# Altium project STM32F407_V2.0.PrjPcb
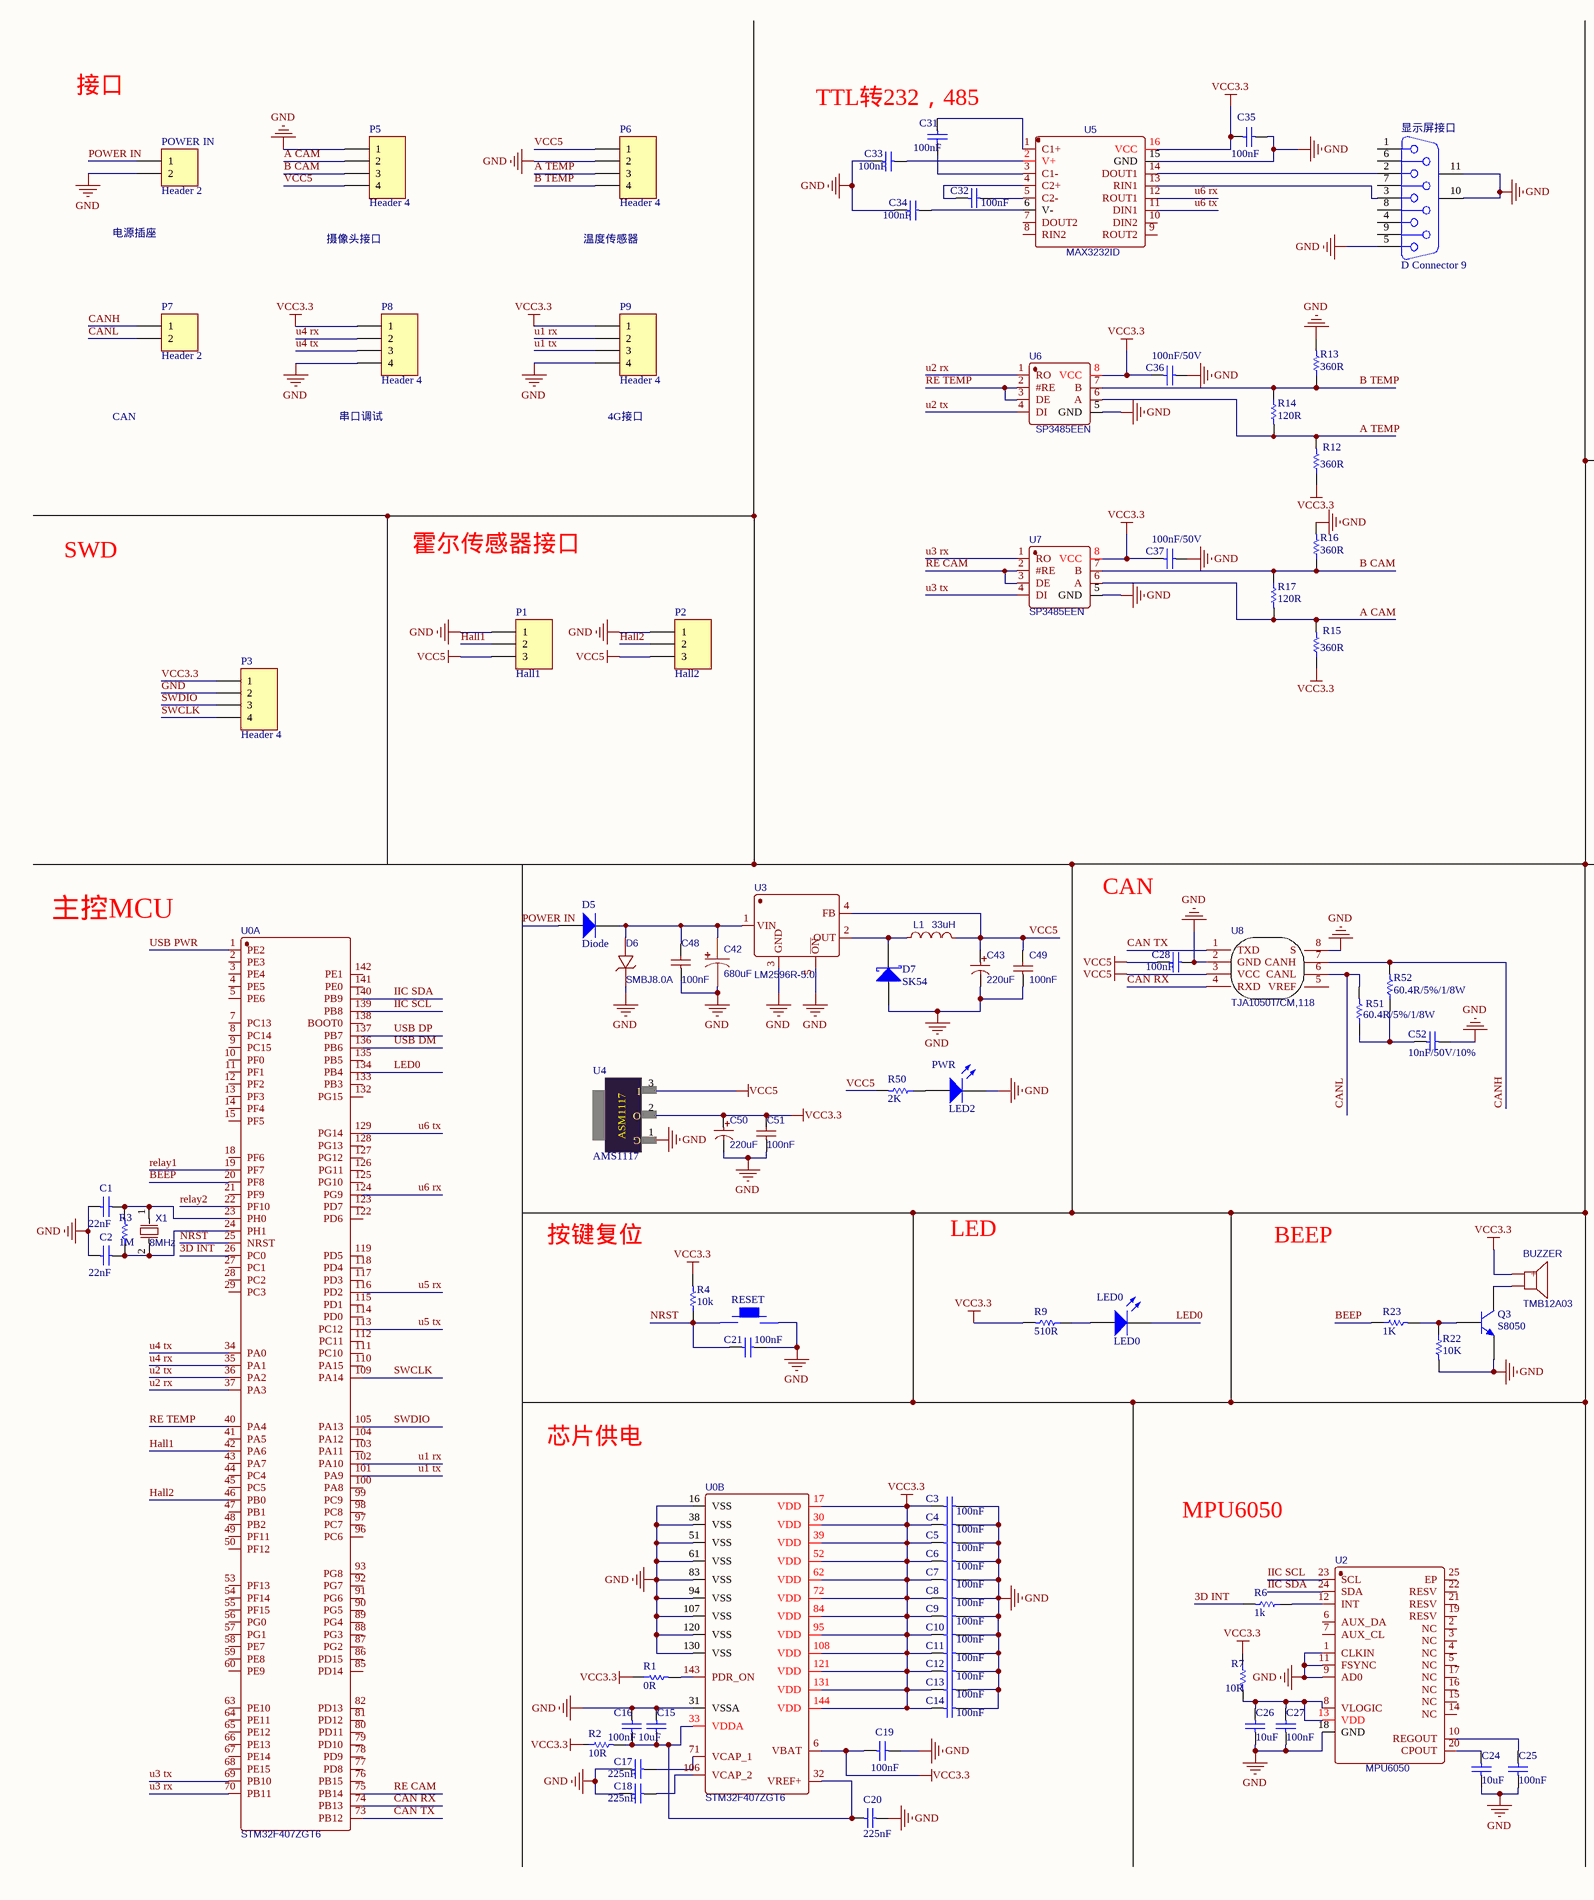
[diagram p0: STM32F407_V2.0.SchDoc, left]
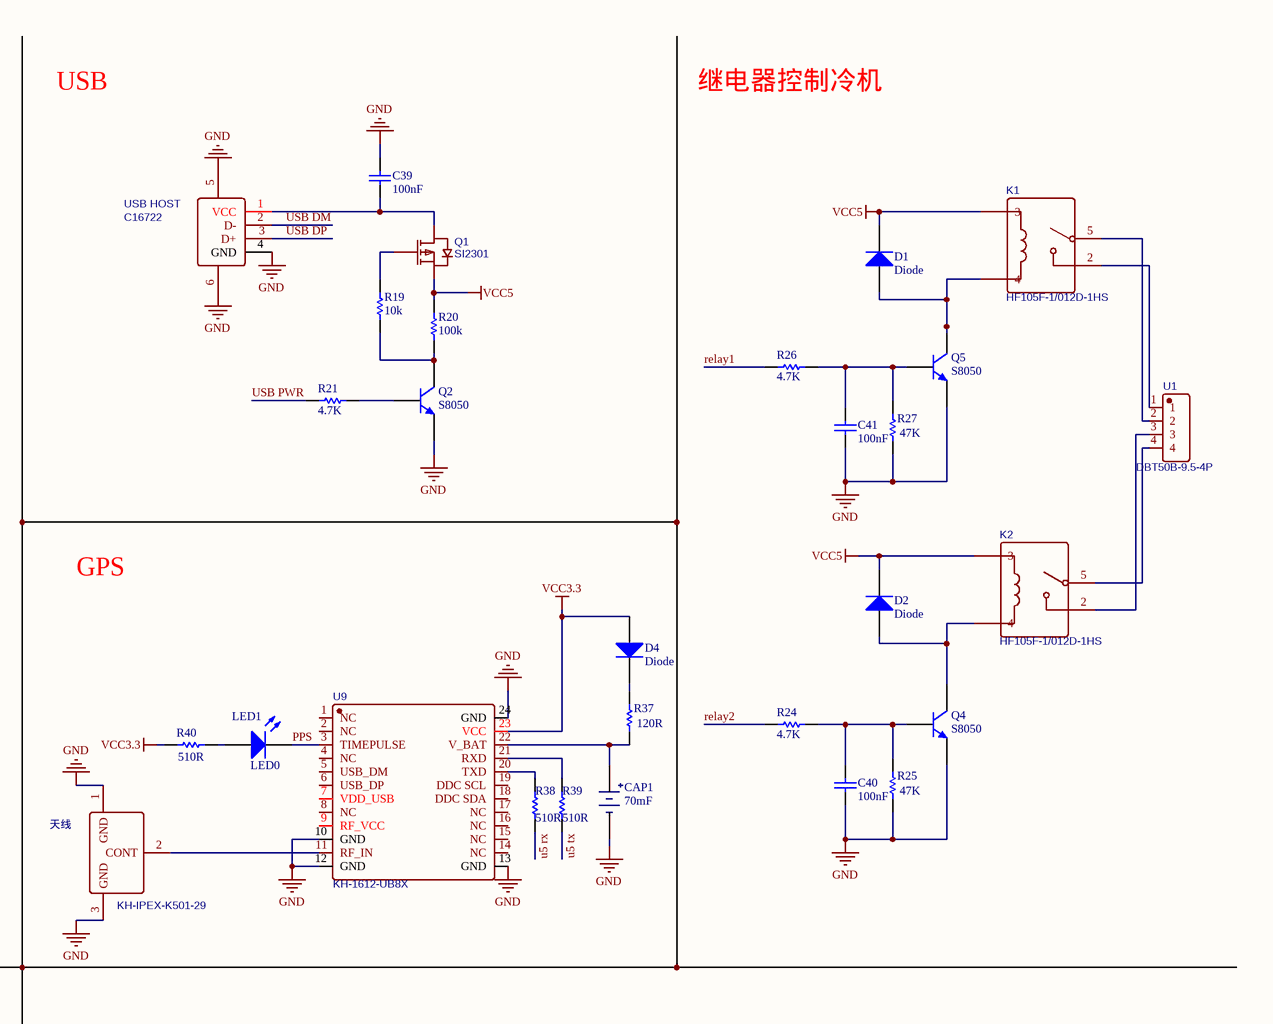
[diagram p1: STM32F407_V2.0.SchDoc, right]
1 sheet, 115 parts. Net scope: global (net labels, ports and power ports of the same name join across sheets).
Board file: STM32F407_V2.0.PcbDoc

## Sheet STM32F407_V2.0.SchDoc
size A2

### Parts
BUZZER  TMB12A03  [BUZ-TH_BD12.0-P7.60-D0.6-FD]
C1  22nF  [SMD_CAP_0603]
C2  22nF  [SMD_CAP_0603]
C3  100nF  [SMD_CAP_0603]
C4  100nF  [SMD_CAP_0603]
C5  100nF  [SMD_CAP_0603]
C6  100nF  [SMD_CAP_0603]
C7  100nF  [SMD_CAP_0603]
C8  100nF  [SMD_CAP_0603]
C9  100nF  [SMD_CAP_0603]
C10  100nF  [SMD_CAP_0603]
C11  100nF  [SMD_CAP_0603]
C12  100nF  [SMD_CAP_0603]
C13  100nF  [SMD_CAP_0603]
C14  100nF  [SMD_CAP_0603]
C15  10uF  [SMD_CAP_0603]
C16  100nF  [SMD_CAP_0603]
C17  225nF  [SMD_CAP_0603]
C18  225nF  [SMD_CAP_0603]
C19  100nF  [SMD_CAP_0603]
C20  225nF  [SMD_CAP_0603]
C21  100nF  [SMD_CAP_0603]
C24  10uF  [SMD_CAP_0603]
C25  100nF  [SMD_CAP_0603]
C26  10uF  [SMD_CAP_0603]
C27  100nF  [SMD_CAP_0603]
C28  100nF  [SMD_CAP_0603]
C31  100nF  [SMD_CAP_0603]
C32  100nF  [SMD_CAP_0603]
C33  100nF  [SMD_CAP_0603]
C34  100nF  [SMD_CAP_0603]
C35  100nF  [SMD_CAP_0603]
C36  100nF/50V  [SMD_CAP_0603]
C37  100nF/50V  [SMD_CAP_0603]
C39  100nF  [SMD_CAP_0603]
C40  100nF  [SMD_CAP_0603]
C41  100nF  [SMD_CAP_0603]
C42  680uF  [CAP-TH_BD8.0-P3.50-D1.0-FD]
C43  220uF  [CAP-TH_BD8.0-P3.50-D1.0-FD]
C48  100nF  [SMD_CAP_0603]
C49  100nF  [SMD_CAP_0603]
C50  220uF  [CAP-TH_BD8.0-P3.50-D1.0-FD]
C51  100nF  [SMD_CAP_0603]
C52  10nF/50V/10%  [SMD_CAP_0603]
CAP1  70mF  [CAP-TH_XH414HG]
D1  Diode  [SMC]
D2  Diode  [SMC]
D4  Diode  [SMC]
D5  Diode  [SMC]
D6  SMBJ8.0A  [SMB_L4.6-W3.6-LS5.3-RD]
D7  SK54  [SMB]
K1  HF105F-1/012D-1HS  [RELAY-TH_HF105F-XXX-1HXXX-XXX]
K2  HF105F-1/012D-1HS  [RELAY-TH_HF105F-XXX-1HXXX-XXX]
L1  33uH  [IND-SMD_L7.0-W6.8]
LED0  LED0  [3.2X1.6X1.1]
LED1  LED0  [3.2X1.6X1.1]
P1  Hall1  [HDR1X3]
P2  Hall2  [HDR1X3]
P3  Header 4  [HDR1X4]
P5  Header 4  [HDR1X4]
P6  Header 4  [HDR1X4]
P7  Header 2  [HDR1X2]
P8  Header 4  [HDR1X4]
P9  Header 4  [HDR1X4]
POWER_IN  Header 2  [HDR1X2]
PWR  LED2  [3.2X1.6X1.1]
Q1  SI2301  [SOT-23-3_L2.9-W1.3-P1.90-LS2.4-BR]
Q2  S8050  [NUP2105LT1G]
Q3  S8050  [NUP2105LT1G]
Q4  S8050  [NUP2105LT1G]
Q5  S8050  [NUP2105LT1G]
R1  0R  [SMD_RES_0603]
R2  10R  [SMD_RES_0603]
R3  1M  [SMD_RES_0603]
R4  10k  [SMD_RES_0603]
R6  1k  [SMD_RES_0603]
R7  10R  [SMD_RES_0603]
R9  510R  [SMD_RES_0603]
R12  360R  [SMD_RES_0603]
R13  360R  [SMD_RES_0603]
R14  120R  [SMD_RES_0603]
R15  360R  [SMD_RES_0603]
R16  360R  [SMD_RES_0603]
R17  120R  [SMD_RES_0603]
R19  10k  [SMD_RES_0603]
R20  100k  [SMD_RES_0603]
R21  4.7K  [SMD_RES_0603]
R22  10K  [SMD_RES_0603]
R23  1K  [SMD_RES_0603]
R24  4.7K  [SMD_RES_0603]
R25  47K  [SMD_RES_0603]
R26  4.7K  [SMD_RES_0603]
R27  47K  [SMD_RES_0603]
R37  120R  [SMD_RES_0603]
R38  510R  [SMD_RES_0603]
R39  510R  [SMD_RES_0603]
R40  510R  [SMD_RES_0603]
R50  2K  [SMD_RES_0603]
R51  60.4R/5%/1/8W  [SMD_RES_0603]
R52  60.4R/5%/1/8W  [SMD_RES_0603]
RESET  SW  [SW-TH_4P-L6.0-W6.0-P4.50-LS6.5]  (value not drawn)
U0  STM32F407ZGT6  [LQFP-144_L20.0-W20.0-P0.50-LS22.0-BL]  (parts A,B of 2)
U1  DBT50B-9.5-4P  [CONN-TH_DBT50B-9.5-4P]
U2  MPU6050  [QFN-24_L4.0-W4.0-P0.50-BL-EP2.6]
U3  LM2596R-5.0  [TO-263-5_L10.2-W8.6-P1.70-LS14.4-TL]
U4  AMS1117  [SOT-223_L6.7-W3.5-P2.30-BR]
U5  MAX3232ID  [SOIC-16_L9.9-W3.9-P1.27-LS6.0-BL]
U6  SP3485EEN  [SOP-8_L5.0-W4.0-P1.27-LS6.0-BL]
U7  SP3485EEN  [SOP-8_L5.0-W4.0-P1.27-LS6.0-BL]
U8  TJA1050T/CM,118  [SOIC-8_L5.0-W4.0-P1.27-LS6.0-BL]
U9  KH-1612-UB8X  [GPSM-SMD_KH-1612-UBXX]
USB_HOST  C16722  [USB-A-TH_4P-V-F_13.7MM]
X1  8MHz  [HC-49S_L11.4-W4.8]
天线  KH-IPEX-K501-29  [ANT-SMD_KH-IPEX-K501-29]
显示屏接口  D Connector 9  [DSUB1.385-2H9]

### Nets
GND: C1.2 C2.2 C3.2 C4.2 C5.2 C6.2 C7.2 C8.2 C9.2 C10.2 C11.2 C12.2 C13.2 C14.2 C15.2 C16.2 C17.2 C18.2 C19.1 C20.2 C21.1 C24.1 C25.1 C26.1 C27.1 C28.2 C33.1 C34.1 C35.2 C36.2 C37.2 C39.1 C40.2 C41.2 C42.2 C43.2 C48.1 C49.1 C50.2 C51.1 C52.2 CAP1.2 D6.1 D7.1(A) P1.1 P2.1 P3.2 P5.1 P6.2 P8.4 P9.4 POWER_IN.2 PWR.2(K) Q2.3(E) Q3.3(E) Q4.3(E) Q5.3(E) R13.2 R16.2 R22.2 R25.2 R27.2 RESET.3 U0.16(VSS) U0.31(VSSA) U0.38(VSS) U0.51(VSS) U0.61(VSS) U0.83(VSS) U0.94(VSS) U0.107(VSS) U0.120(VSS) U0.130(VSS) U2.1(CLKIN) U2.9(AD0) U2.11(FSYNC) U2.18(GND) U3.3(GND) U3.5(~{ON}) U4.1 U5.15(GND) U6.5(GND) U7.5(GND) U8.2(GND) U8.8(S) U9.10(GND) U9.12(GND) U9.13(GND) U9.24(GND) USB_HOST.4(GND) USB_HOST.5(SH1) USB_HOST.6(SH2) 天线.1(GND) 天线.3(GND) 显示屏接口.5 显示屏接口.10(MH1) 显示屏接口.11(MH2)
VCC3.3: BUZZER.1(+) C3.1 C4.1 C5.1 C6.1 C7.1 C8.1 C9.1 C10.1 C11.1 C12.1 C13.1 C14.1 C19.2 C35.1 C36.1 C37.1 C50.1 C51.2 D4.1(A) P3.1 P8.1 P9.1 R1.1 R4.2 R7.1 R9.2 R12.1 R15.1 R40.2 U0.6(VBAT) U0.17(VDD) U0.30(VDD) U0.39(VDD) U0.52(VDD) U0.62(VDD) U0.72(VDD) U0.84(VDD) U0.95(VDD) U0.108(VDD) U0.121(VDD) U0.131(VDD) U0.144(VDD) U4.2 U5.16(VCC) U6.8(VCC) U7.8(VCC) U9.23(VCC)
VCC5: C28.1 C43.1 C49.2 D1.2(K) D2.2(K) K1.3 K2.3 L1.2 P1.3 P2.3 P5.4 P6.1 Q1.2(S) R20.2 R50.2 U3.4(FB) U4.3 U8.3(VCC)
3D INT: R6.2 U0.26(PC0)
A CAM: P5.2 R15.2 R17.2 U7.6(A)
A TEMP: P6.3 R12.2 R14.2 U6.6(A)
B CAM: P5.3 R16.1 R17.1 U7.7(B)
B TEMP: P6.4 R13.1 R14.1 U6.7(B)
BEEP: R23.1 U0.20(PF8)
CAN RX: U0.74(PB13) U8.4(RXD)
CAN TX: U0.73(PB12) U8.1(TXD)
CANH: P7.1 R52.2 U8.7(CANH)
CANL: P7.2 R51.2 U8.6(CANL)
Hall1: P1.2 U0.42(PA6)
Hall2: P2.2 U0.46(PB0)
IIC SCL: U0.139(PB8) U2.23(SCL)
IIC SDA: U0.140(PB9) U2.24(SDA)
LED0: LED0.2(K) U0.134(PB4)
NRST: C21.2 R4.1 RESET.1 U0.25(NRST)
POWER IN: D5.1(A) POWER_IN.1
PPS: LED1.2(K) U9.3(TIMEPULSE)
RE CAM: U0.75(PB14) U7.2(#RE) U7.3(DE)
RE TEMP: U0.40(PA4) U6.2(#RE) U6.3(DE)
relay1: R26.2 U0.19(PF7)
relay2: R24.2 U0.22(PF10)
SWCLK: P3.4 U0.109(PA14)
SWDIO: P3.3 U0.105(PA13)
u1 rx: P9.2 U0.102(PA10)
u1 tx: P9.3 U0.101(PA9)
u2 rx: U0.37(PA3) U6.1(RO)
u2 tx: U0.36(PA2) U6.4(DI)
u3 rx: U0.70(PB11) U7.1(RO)
u3 tx: U0.69(PB10) U7.4(DI)
u4 rx: P8.2 U0.35(PA1)
u4 tx: P8.3 U0.34(PA0)
u5 rx: R38.1 U0.116(PD2)
u5 tx: R39.1 U0.113(PC12)
u6 rx: U0.124(PG9) U5.12(ROUT1)
u6 tx: U0.129(PG14) U5.11(DIN1)
USB DM: U0.136(PB6) USB_HOST.2(D-)
USB DP: U0.137(PB7) USB_HOST.3(D+)
USB PWR: R21.2 U0.1(PE2)
NetBUZZER_2: BUZZER.2 Q3.1(C)
NetC1_1: C1.1 R3.2 U0.23(PH0) X1.1(OSC1)
NetC2_1: C2.1 R3.1 U0.24(PH1) X1.2(OSC2)
NetC15_1: C15.1 C16.1 C20.1 R2.2 U0.32(VREF+) U0.33(VDDA)
NetC17_1: C17.1 U0.71(VCAP_1)
NetC18_1: C18.1 U0.106(VCAP_2)
NetC24_2: C24.2 U2.20(CPOUT)
NetC25_2: C25.2 U2.10(REGOUT)
NetC26_2: C26.2 C27.2 R7.2 U2.8(VLOGIC) U2.13(VDD)
NetC31_1: C31.1 U5.1(C1+)
NetC31_2: C31.2 U5.3(C1-)
NetC32_1: C32.1 U5.4(C2+)
NetC32_2: C32.2 U5.5(C2-)
NetC33_2: C33.2 U5.2(V+)
NetC34_2: C34.2 U5.6(V-)
NetC39_2: C39.2 Q1.1(G) USB_HOST.1(VCC)
NetC40_1: C40.1 Q4.2(B) R24.1 R25.1
NetC41_1: C41.1 Q5.2(B) R26.1 R27.1
NetC42_1: C42.1 C48.2 D5.2(K) D6.2 U3.1(VIN)
NetC52_1: C52.1 R51.1 R52.1
NetCAP1_1: CAP1.1 R37.1 U9.22(V_BAT)
NetD1_1: D1.1(A) K1.4 Q5.1(C)
NetD2_1: D2.1(A) K2.4 Q4.1(C)
NetD4_2: D4.2(K) R37.2
NetD7_2: D7.2(K) L1.1 U3.2(OUT)
NetK1_2: K1.2 U1.1
NetK1_5: K1.5 U1.2
NetK2_2: K2.2 U1.3
NetK2_5: K2.5 U1.4
NetLED0_1: LED0.1(A) R9.1
NetLED1_1: LED1.1(A) R40.1
NetPWR_1: PWR.1(A) R50.1
NetQ1_3: Q1.3(D) R19.2
NetQ2_1: Q2.1(C) R19.1 R20.1
NetQ2_2: Q2.2(B) R21.1
NetQ3_2: Q3.2(B) R22.1 R23.2
NetR1_2: R1.2 U0.143(PDR_ON)
NetR6_1: R6.1 U2.12(INT)
NetR38_2: R38.2 U9.20(TXD)
NetR39_2: R39.2 U9.21(RXD)
NetU5_13: U5.13(RIN1) 显示屏接口.3
NetU5_14: U5.14(DOUT1) 显示屏接口.2
NetU9_11: U9.11(RF_IN) 天线.2(CONT)

Not connected (* = marked no-connect by the designer): R2 1; U0 2(PE3) 3(PE4) 4(PE5) 5(PE6) 7(PC13) 8(PC14) 9(PC15) 10(PF0) 11(PF1) 12(PF2) 13(PF3) 14(PF4) 15(PF5) 18(PF6) 21(PF9) 27(PC1) 28(PC2) 29(PC3) 41(PA5) 43(PA7) 44(PC4) 45(PC5) 47(PB1) 48(PB2) 49(PF11) 50(PF12) 53(PF13) 54(PF14) 55(PF15) 56(PG0) 57(PG1) 58(PE7) 59(PE8) 60(PE9) 63(PE10) 64(PE11) 65(PE12) 66(PE13) 67(PE14) 68(PE15) 76(PB15) 77(PD8) 78(PD9) 79(PD10) 80(PD11) 81(PD12) 82(PD13) 85(PD14) 86(PD15) 87(PG2) 88(PG3) 89(PG4) 90(PG5) 91(PG6) 92(PG7) 93(PG8) 96(PC6) 97(PC7) 98(PC8) 99(PC9) 100(PA8) 103(PA11) 104(PA12) 110(PA15) 111(PC10) 112(PC11) 114(PD0) 115(PD1) 117(PD3) 118(PD4) 119(PD5) 122(PD6) 123(PD7) 125(PG10) 126(PG11) 127(PG12) 128(PG13) 132(PG15) 133(PB3) 135(PB5) 138(BOOT0) 141(PE0) 142(PE1); U2 2(NC) 3(NC) 4(NC) 5(NC) 6(AUX_DA) 7(AUX_CL) 14(NC) 15(NC) 16(NC) 17(NC) 19(RESV) 21(RESV) 22(RESV) 25(EP); U5 7(DOUT2) 8(RIN2) 9(ROUT2) 10(DIN2); U8 5(VREF); U9 1(NC) 2(NC) 4(NC) 5(USB_DM) 6(USB_DP) 7(VDD_USB) 8(NC) 9(RF_VCC) 14(NC) 15(NC) 16(NC) 17(NC) 18(DDC_SDA) 19(DDC_SCL); 显示屏接口 1 4 6 7 8 9

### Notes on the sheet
- 接口
- USB
- 继电器控制冷机
- (near C31) TTL转232，485
- 电源插座
- 摄像头接口
- 温度传感器
- CAN
- 串口调试
- 4G接口
- GPS
- SWD
- 霍尔传感器接口
- 主控MCU
- 按键复位
- LED
- BEEP
- 芯片供电
- MPU6050
- Labels drawn without touching a wire or pin: VCC3.3

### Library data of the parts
BUZZER = TMB12A03: 蜂鸣器; BOM_Manufacturer: HNDZ; BOM_Paste Type: expand; BOM_Assembly Type: manualWeld
C1 C2 = Cap: Capacitor; Value: 100uF
C3-C18 C21 C24-C27 = Cap: Capacitor; Value: 100pF
C19 C20 = Cap: 陶瓷电容; Value: 100pF
C28 C31-C37 C39-C41 C52 = Cap: Capacitor; Value: 104
C42 = 680uF: BOM_Manufacturer: Ymin; BOM_Manufacturer Part: LKMD1601E681MF; nameAlias: Capacitance; Contributor: LCSC
C43 C50 = 220uF: BOM_Manufacturer: AISHI; BOM_Manufacturer Part: ERE1VM221F12OT; nameAlias: Capacitance
C48 C49 C51 = 100nF: BOM_Manufacturer: FH; BOM_Manufacturer Part: 1210B104K500NT; nameAlias: Capacitance
CAP1 = Super Cap
D1 D2 D4 D5 = Diode: Default Diode
D6 = SMBJ8.0A_C726816: BOM_Manufacturer: TWGMC; Contributor: LCSC
D7 = D Schottky: Schottky Diode
K1 K2 = HF105F-1/012D-1HS: 继电器; BOM_Manufacturer: Xiamen Hongfa Electroacoustic; Contributor: LCSC; BOM_Paste Type: expand
L1 = 33uH: BOM_Manufacturer: TDK; BOM_Manufacturer Part: SLF7045T-330MR82-PF; nameAlias: Inductance
LED0 LED1 PWR = LED2: Typical RED, GREEN, YELLOW, AMBER GaAs LED
P1 P2 = Header 3: Header, 3-Pin
P3 P5 P6 P8 P9 = Header 4: Header, 4-Pin
P7 POWER_IN = Header 2: Header, 2-Pin
Q1 = SI2301_C427391: BOM_Manufacturer: MDD（Microdiode Electronics）; Contributor: LCSC
Q2-Q5 = NPN: NPN Bipolar Transistor
R1 R2 R4 R6 R7 = Res1: Resistor
R3 = Res1: Resistor; Value: 1K
R9 R40 R50 = Res1: 水泥电阻
R12-R17 R19-R22 R24-R27 R37-R39 R51 R52 = Res Semi: Semiconductor Resistor; Value: 1K
R23 = Res Semi: Semiconductor Resistor
U0 = STM32F407ZGT6: MCU; BOM_Manufacturer: ST; subpart_no: 1; tags: STM32; BOM_Paste Type: recommend; BOM_Assembly Type: smtWeld
U1 = DBT50B-9.5-4P: 接线端子; BOM_Manufacturer: DIBO; Contributor: LCSC; BOM_Paste Type: expand
U2 = MPU-6050_C24112: 陀螺仪; BOM_Manufacturer: InvenSense; sourceId: 1T5FDZYC8; BOM_Paste Type: base
U3 = LM2596R-5.0: BOM_Manufacturer: HTC
U4 = ASM1117
U5 = MAX3232ID: BOM_Manufacturer: Texas Instruments; Contributor: LCSC; BOM_Paste Type: expand
U6 U7 = SP3485EEN: BOM_Manufacturer: UMW(Youtai Semiconductor Co., Ltd.); Contributor: LCSC; BOM_Paste Type: expand
U8 = TJA1050T/CM,118: BOM_Manufacturer: NXP; BOM_Paste Type: base
U9 = KH-1612-UB8X: GPS; BOM_Manufacturer: Shenzhen Kinghelm Elec; Contributor: LCSC
USB_HOST = C16722: USB_HOST; BOM_Manufacturer: Boom Precision Elec; Contributor: LCSC
X1 = 8MHz: 贴片晶振; BOM_Manufacturer: TKD; BOM_Manufacturer Part: CS16M008000RD1; nameAlias: Frequency; Contributor: LCSC
天线 = KH-IPEX-K501-29: 天线插座; BOM_Manufacturer: Shenzhen Kinghelm Elec; Contributor: LCSC; BOM_Paste Type: expand
显示屏接口 = D Connector 9: Receptacle Assembly, 9 Position, Right Angle; PackageDocument: O; Positions: 9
